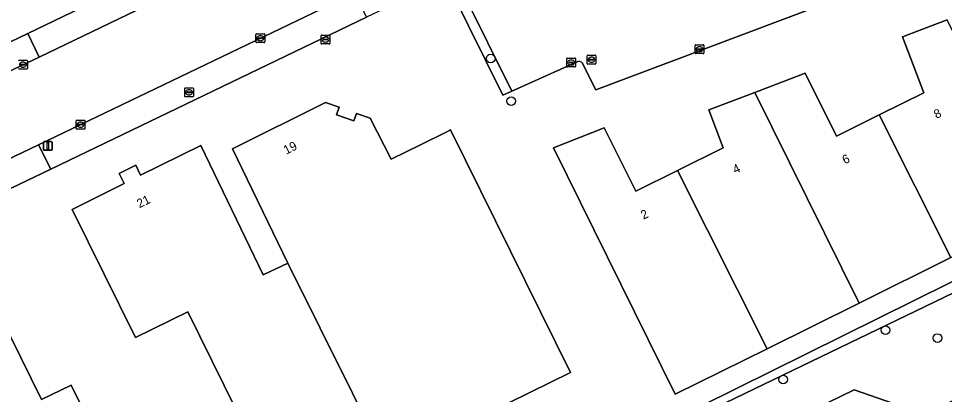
# Model space of a CAD drawing. Extents: x 157692 to 159674, y 381452 to 383291.
# Drawn here: x 158074.3 to 158178.6, y 381634.2 to 381676.6 of the extents above; entities that cross this region are included whole.
import ezdxf

# ---------------------------------------------------------------- set-up
doc = ezdxf.new("R2010")
doc.units = 0
for name, color, linetype in [('IMGEO_Boom', 7, 'Continuous'), ('IMGEO_Brandkraan', 7, 'Continuous'), ('IMGEO_Erf', 7, 'Continuous'), ('IMGEO_Groenvoorziening', 7, 'Continuous'), ('IMGEO_Kolk', 7, 'Continuous'), ('IMGEO_Lichtmast', 7, 'Continuous'), ('IMGEO_Pand', 7, 'Continuous'), ('IMGEO_Pand_nummerreeks', 7, 'Continuous'), ('IMGEO_Parkeervlak_open', 7, 'Continuous'), ('IMGEO_Rijbaan_lokaal_gesloten', 7, 'Continuous'), ('IMGEO_Rioolput', 7, 'Continuous'), ('IMGEO_Voetpad_halfverhard', 7, 'Continuous'), ('IMGEO_Voetpad_open', 7, 'Continuous')]:
    doc.layers.add(name, color=color, linetype=linetype)

msp = doc.modelspace()

# ---------------------------------------------------------------- linework, layer by layer
at = {"layer": 'IMGEO_Boom'}
for centre in [(158127.51, 381672.06), (158129.81, 381667.25), (158171.98, 381641.45), (158177.85, 381640.56), (158160.46, 381635.89)]:
    msp.add_circle(centre, 0.489, dxfattribs=at)
at = {"layer": 'IMGEO_Brandkraan'}
for p, q in [((158093.04, 381667.83), (158093.04, 381668.68)), ((158093.11, 381668.76), (158093.96, 381668.76)), ((158094.04, 381668.68), (158094.04, 381667.83)), ((158093.96, 381667.75), (158093.11, 381667.75)), ((158093.29, 381668.25), (158093.29, 381668.26)), ((158093.73, 381668.21), (158093.33, 381668.21)), ((158093.34, 381668.3), (158093.74, 381668.3)), ((158093.52, 381668.53), (158093.55, 381668.53)), ((158093.55, 381667.98), (158093.52, 381667.98)), ((158093.78, 381668.26), (158093.78, 381668.25))]:
    msp.add_line(p, q, dxfattribs=at)
for points in [[(158093.04, 381667.83), (158093.04, 381668.68)], [(158093.11, 381668.76), (158093.96, 381668.76)], [(158094.04, 381668.68), (158094.04, 381667.83)], [(158093.96, 381667.75), (158093.11, 381667.75)]]:
    msp.add_lwpolyline(points, dxfattribs=at)
for centre, radius, start, end in [((158093.11, 381668.68), 0.0765, 91.552, 178.448), ((158093.11, 381668.68), 0.0765, 91.552, 178.448), ((158093.96, 381668.68), 0.0765, 1.552, 88.448), ((158093.96, 381668.68), 0.0765, 1.552, 88.448), ((158093.11, 381667.83), 0.0765, 181.552, 268.448), ((158093.11, 381667.83), 0.0765, 181.552, 268.448), ((158093.34, 381668.26), 0.0403, 85.8775, 175.7526), ((158093.33, 381668.25), 0.0366, 178.938, 274.7102), ((158093.74, 381668.25), 0.043, 264.8664, 352.4533), ((158093.74, 381668.26), 0.0386, 1.7309, 96.639), ((158093.96, 381667.83), 0.0765, 271.552, 358.448), ((158093.96, 381667.83), 0.0765, 271.552, 358.448)]:
    msp.add_arc(centre, radius, start, end, dxfattribs=at)
for centre, major_axis, ratio, start_param, end_param in [((158093.52, 381668.25), (-0.387, 0.002), 0.722429, 4.712389, 7.853982), ((158093.55, 381668.25), (-0.39, 0.002), 0.717154, 1.570796, 4.712389)]:
    msp.add_ellipse(centre, major_axis=major_axis, ratio=ratio, start_param=start_param, end_param=end_param, dxfattribs=at)
at = {"layer": 'IMGEO_Erf'}
for points in [[(158006.88, 381609.08), (158005.9, 381627.87), (158005.47, 381636.38), (158005.22, 381641.11), (158032.78, 381654.36), (158038.28, 381657), (158060.57, 381667.76), (158067.21, 381670.95), (158069.61, 381672.13), (158075.38, 381674.88), (158095.21, 381684.45), (158107.37, 381690.34), (158121.32, 381697.1), (158122.88, 381701.31), (158109.4, 381729.27), (158106.88, 381734.58), (158102.55, 381743.61), (158102.33, 381744.05), (158099.75, 381749.47), (158099.5, 381750), (158086.3, 381777.42), (158083.31, 381783.63), (158080.66, 381789.14)], [(158209.52, 381694.97), (158139.36, 381668.54), (158137.83, 381671.58)], [(158024.82, 381594.04), (158031.77, 381579.97), (158034.87, 381573.76), (158035.24, 381573.03), (158037.88, 381567.78), (158119.21, 381608.01), (158123.9, 381610.33), (158120.64, 381617.17), (158120.43, 381617.61), (158147.17, 381630.9), (158223.29, 381668.59), (158222.29, 381671.21), (158214.04, 381692.91)], [(158137.27, 381671.68), (158129.91, 381668.4), (158128.88, 381667.94), (158123.05, 381679.74), (158122.43, 381681), (158119.71, 381679.69), (158113.54, 381676.71), (158077.96, 381659.61), (158067.11, 381654.39), (158048.67, 381645.55), (158046.69, 381644.6), (158042.44, 381642.56), (158040.6, 381641.67), (158025.19, 381634.25)], [(158179.33, 381649.62), (158169.02, 381644.5), (158158.66, 381639.36), (158148.3, 381634.22), (158134.57, 381661.98), (158140.31, 381664.26), (158143.85, 381657.12), (158148.56, 381659.46), (158153.69, 381662), (158152.07, 381666.27), (158157.26, 381668.25), (158162.95, 381670.42), (158166.47, 381663.32), (158171.28, 381665.7), (158176.31, 381668.2), (158173.91, 381674.52), (158178.92, 381676.42)], [(158104.27, 381621.43), (158093.39, 381643.51), (158087.49, 381640.61), (158080.35, 381655.06), (158086.21, 381657.98), (158085.66, 381659.1), (158087.52, 381660.04), (158088.08, 381658.9), (158094.86, 381662.26), (158101.9, 381647.68), (158104.65, 381649), (158098.44, 381661.87), (158108.91, 381667.1), (158110.46, 381666.56), (158110.16, 381665.72), (158112.11, 381665.03), (158112.4, 381665.87), (158113.95, 381665.33), (158116.3, 381660.71), (158119.67, 381662.38), (158122.42, 381663.74), (158123, 381664.03), (158136.52, 381636.69), (158115.88, 381626.52)]]:
    msp.add_lwpolyline(points, dxfattribs=at)
msp.add_lwpolyline([(158076.91, 381633.62), (158080.25, 381635.26), (158087.76, 381620.07), (158093.61, 381608.23), (158090.03, 381606.46), (158091.23, 381603.97), (158082.69, 381599.75), (158081.47, 381602.22), (158081.08, 381602.03), (158075.22, 381613.87), (158063.04, 381638.49), (158059.37, 381636.67), (158057.99, 381639.46), (158061.69, 381641.28), (158061.07, 381642.53), (158065.51, 381644.72), (158065.68, 381644.38), (158066.32, 381643.1), (158068.5, 381644.18), (158071.05, 381645.45)], close=True, dxfattribs=at)
msp.add_arc((158137.47, 381671.17), 0.548, 49.3378, 111.5714, dxfattribs=at)
at = {"layer": 'IMGEO_Groenvoorziening'}
msp.add_lwpolyline([(158463.02, 381784.54), (158461.03, 381788.17), (158441.98, 381777.74), (158416.14, 381764.39), (158259.62, 381686.58), (158254.34, 381683.97), (158223.29, 381668.59), (158147.17, 381630.9), (158120.43, 381617.61), (158120.64, 381617.17), (158179.73, 381645.71), (158182.9, 381642.9), (158254.91, 381679.12), (158392.17, 381750), (158448.48, 381779.08), (158459.69, 381785.07)], dxfattribs=at)
for points in [[(158373.93, 381726.17), (158393.92, 381735.29), (158410.81, 381742.32), (158409.27, 381746.01), (158392.39, 381738.98), (158372.39, 381729.87), (158258.55, 381675.61), (158257.98, 381676.74), (158256.56, 381676.02), (158222.08, 381658.49), (158184.33, 381640.13), (158182.9, 381642.9), (158179.73, 381645.71), (158120.64, 381617.17), (158123.9, 381610.33), (158119.21, 381608.01), (158121.49, 381605.85), (158133.24, 381611.46), (158134.78, 381618.29), (158168.47, 381634.73), (158176.33, 381632), (158260.34, 381672.04), (158264.52, 381674.03)], [(158133.24, 381611.46), (158176.33, 381632), (158168.47, 381634.73), (158134.78, 381618.29)]]:
    msp.add_lwpolyline(points, close=True, dxfattribs=at)
at = {"layer": 'IMGEO_Kolk'}
for p, q in [((158101.05, 381673.93), (158101.05, 381674.78)), ((158101.13, 381674.85), (158101.98, 381674.85)), ((158101.98, 381673.85), (158101.13, 381673.85)), ((158101.31, 381674.35), (158101.31, 381674.36)), ((158101.75, 381674.31), (158101.35, 381674.31)), ((158101.36, 381674.4), (158101.75, 381674.4)), ((158101.54, 381674.63), (158101.57, 381674.63)), ((158101.56, 381674.07), (158101.54, 381674.07)), ((158101.8, 381674.36), (158101.8, 381674.35)), ((158102.06, 381674.78), (158102.06, 381673.93)), ((158108.4, 381673.77), (158108.4, 381674.62)), ((158108.48, 381674.7), (158109.33, 381674.7)), ((158108.66, 381674.19), (158108.66, 381674.2)), ((158109.1, 381674.15), (158108.7, 381674.15)), ((158108.71, 381674.24), (158109.1, 381674.24)), ((158108.89, 381674.48), (158108.92, 381674.48)), ((158108.91, 381673.92), (158108.89, 381673.92)), ((158109.15, 381674.2), (158109.15, 381674.19)), ((158109.41, 381674.62), (158109.41, 381673.77)), ((158109.33, 381673.7), (158108.48, 381673.7)), ((158150.54, 381672.69), (158150.54, 381673.54)), ((158150.61, 381673.62), (158151.47, 381673.62)), ((158150.8, 381673.11), (158150.8, 381673.12)), ((158150.84, 381673.16), (158151.24, 381673.16)), ((158151.24, 381673.07), (158150.84, 381673.07)), ((158151.05, 381672.84), (158151.02, 381672.84)), ((158151.03, 381673.39), (158151.05, 381673.39)), ((158151.28, 381673.12), (158151.28, 381673.11)), ((158151.54, 381673.54), (158151.54, 381672.69)), ((158074.4, 381671.88), (158075.25, 381671.88)), ((158075.32, 381671.8), (158075.32, 381670.95)), ((158136.08, 381671.18), (158136.08, 381672.04)), ((158136.15, 381672.11), (158137, 381672.11)), ((158136.56, 381671.89), (158136.59, 381671.89)), ((158137.08, 381672.04), (158137.08, 381671.18)), ((158151.47, 381672.61), (158150.61, 381672.61)), ((158075.25, 381670.87), (158074.4, 381670.87)), ((158074.58, 381671.37), (158074.58, 381671.38)), ((158075.02, 381671.33), (158074.62, 381671.33)), ((158074.63, 381671.42), (158075.02, 381671.42)), ((158074.81, 381671.65), (158074.84, 381671.65)), ((158074.83, 381671.1), (158074.81, 381671.1)), ((158075.07, 381671.38), (158075.07, 381671.37)), ((158137, 381671.11), (158136.15, 381671.11)), ((158136.33, 381671.6), (158136.33, 381671.62)), ((158136.77, 381671.57), (158136.37, 381671.57)), ((158136.38, 381671.65), (158136.78, 381671.65)), ((158136.59, 381671.33), (158136.56, 381671.33)), ((158136.82, 381671.62), (158136.82, 381671.6)), ((158080.81, 381664.19), (158080.81, 381665.04)), ((158080.89, 381665.11), (158081.74, 381665.11)), ((158081.07, 381664.61), (158081.07, 381664.62)), ((158081.51, 381664.57), (158081.11, 381664.57)), ((158081.12, 381664.66), (158081.51, 381664.66)), ((158081.3, 381664.89), (158081.33, 381664.89)), ((158081.56, 381664.62), (158081.56, 381664.61)), ((158081.81, 381665.04), (158081.81, 381664.19)), ((158081.74, 381664.11), (158080.89, 381664.11)), ((158081.32, 381664.33), (158081.3, 381664.33))]:
    msp.add_line(p, q, dxfattribs=at)
for points in [[(158101.05, 381673.93), (158101.05, 381674.78)], [(158101.13, 381674.85), (158101.98, 381674.85)], [(158101.98, 381673.85), (158101.13, 381673.85)], [(158102.06, 381674.78), (158102.06, 381673.93)], [(158108.4, 381673.77), (158108.4, 381674.62)], [(158108.48, 381674.7), (158109.33, 381674.7)], [(158109.41, 381674.62), (158109.41, 381673.77)], [(158109.33, 381673.7), (158108.48, 381673.7)], [(158150.54, 381672.69), (158150.54, 381673.54)], [(158150.61, 381673.62), (158151.47, 381673.62)], [(158151.54, 381673.54), (158151.54, 381672.69)], [(158074.4, 381671.88), (158075.25, 381671.88)], [(158075.32, 381671.8), (158075.32, 381670.95)], [(158136.08, 381671.18), (158136.08, 381672.04)], [(158136.15, 381672.11), (158137, 381672.11)], [(158137.08, 381672.04), (158137.08, 381671.18)], [(158151.47, 381672.61), (158150.61, 381672.61)], [(158075.25, 381670.87), (158074.4, 381670.87)], [(158137, 381671.11), (158136.15, 381671.11)], [(158080.81, 381664.19), (158080.81, 381665.04)], [(158080.89, 381665.11), (158081.74, 381665.11)], [(158081.81, 381665.04), (158081.81, 381664.19)], [(158081.74, 381664.11), (158080.89, 381664.11)]]:
    msp.add_lwpolyline(points, dxfattribs=at)
for centre, radius, start, end in [((158101.13, 381674.78), 0.0765, 91.552, 178.448), ((158101.13, 381674.78), 0.0765, 91.552, 178.448), ((158101.13, 381673.93), 0.0765, 181.552, 268.448), ((158101.13, 381673.93), 0.0765, 181.552, 268.448), ((158101.35, 381674.36), 0.0403, 85.8775, 175.7526), ((158101.35, 381674.35), 0.0366, 178.938, 274.7102), ((158101.76, 381674.36), 0.0386, 1.7309, 96.639), ((158101.75, 381674.35), 0.043, 264.8664, 352.4533), ((158101.98, 381674.78), 0.0765, 1.552, 88.448), ((158101.98, 381674.78), 0.0765, 1.552, 88.448), ((158101.98, 381673.93), 0.0765, 271.552, 358.448), ((158101.98, 381673.93), 0.0765, 271.552, 358.448), ((158108.48, 381674.62), 0.0765, 91.552, 178.448), ((158108.48, 381674.62), 0.0765, 91.552, 178.448), ((158108.7, 381674.2), 0.0403, 85.8775, 175.7526), ((158108.7, 381674.19), 0.0366, 178.938, 274.7102), ((158109.11, 381674.2), 0.0386, 1.7309, 96.639), ((158109.1, 381674.2), 0.043, 264.8664, 352.4533), ((158109.33, 381674.62), 0.0765, 1.552, 88.448), ((158109.33, 381674.62), 0.0765, 1.552, 88.448), ((158108.48, 381673.77), 0.0765, 181.552, 268.448), ((158108.48, 381673.77), 0.0765, 181.552, 268.448), ((158109.33, 381673.77), 0.0765, 271.552, 358.448), ((158109.33, 381673.77), 0.0765, 271.552, 358.448), ((158150.62, 381673.54), 0.0765, 91.552, 178.448), ((158150.62, 381673.54), 0.0765, 91.552, 178.448), ((158150.84, 381673.12), 0.0403, 85.8775, 175.7526), ((158150.83, 381673.11), 0.0366, 178.938, 274.7102), ((158151.24, 381673.12), 0.0386, 1.7309, 96.639), ((158151.24, 381673.11), 0.043, 264.8664, 352.4533), ((158151.46, 381673.54), 0.0765, 1.552, 88.448), ((158151.46, 381673.54), 0.0765, 1.552, 88.448), ((158074.4, 381671.8), 0.0765, 91.552, 178.448), ((158074.4, 381671.8), 0.0765, 91.552, 178.448), ((158075.25, 381671.8), 0.0765, 1.552, 88.448), ((158075.25, 381671.8), 0.0765, 1.552, 88.448), ((158136.15, 381672.04), 0.0765, 91.552, 178.448), ((158136.15, 381672.04), 0.0765, 91.552, 178.448), ((158137, 381672.04), 0.0765, 1.552, 88.448), ((158137, 381672.04), 0.0765, 1.552, 88.448), ((158150.62, 381672.69), 0.0765, 181.552, 268.448), ((158150.62, 381672.69), 0.0765, 181.552, 268.448), ((158151.46, 381672.69), 0.0765, 271.552, 358.448), ((158151.46, 381672.69), 0.0765, 271.552, 358.448), ((158074.4, 381670.95), 0.0765, 181.552, 268.448), ((158074.4, 381670.95), 0.0765, 181.552, 268.448), ((158074.62, 381671.38), 0.0403, 85.8775, 175.7526), ((158074.62, 381671.37), 0.0366, 178.938, 274.7102), ((158075.03, 381671.38), 0.0386, 1.7309, 96.639), ((158075.02, 381671.37), 0.043, 264.8664, 352.4533), ((158075.25, 381670.95), 0.0765, 271.552, 358.448), ((158075.25, 381670.95), 0.0765, 271.552, 358.448), ((158136.15, 381671.19), 0.0765, 181.552, 268.448), ((158136.15, 381671.19), 0.0765, 181.552, 268.448), ((158136.38, 381671.61), 0.0403, 85.8775, 175.7526), ((158136.37, 381671.6), 0.0366, 178.938, 274.7102), ((158136.78, 381671.61), 0.043, 264.8664, 352.4533), ((158136.78, 381671.62), 0.0386, 1.7309, 96.639), ((158137, 381671.19), 0.0765, 271.552, 358.448), ((158137, 381671.19), 0.0765, 271.552, 358.448), ((158080.89, 381665.04), 0.0765, 91.552, 178.448), ((158080.89, 381665.04), 0.0765, 91.552, 178.448), ((158081.11, 381664.62), 0.0403, 85.8775, 175.7526), ((158081.11, 381664.61), 0.0366, 178.938, 274.7102), ((158081.52, 381664.62), 0.0386, 1.7309, 96.639), ((158081.51, 381664.61), 0.043, 264.8664, 352.4533), ((158081.74, 381665.04), 0.0765, 1.552, 88.448), ((158081.74, 381665.04), 0.0765, 1.552, 88.448), ((158080.89, 381664.19), 0.0765, 181.552, 268.448), ((158080.89, 381664.19), 0.0765, 181.552, 268.448), ((158081.74, 381664.19), 0.0765, 271.552, 358.448), ((158081.74, 381664.19), 0.0765, 271.552, 358.448)]:
    msp.add_arc(centre, radius, start, end, dxfattribs=at)
for centre, major_axis, ratio, start_param, end_param in [((158101.54, 381674.35), (-0.387, 0.002), 0.722429, 4.712389, 7.853982), ((158101.57, 381674.35), (-0.39, 0.002), 0.717154, 1.570796, 4.712389), ((158108.89, 381674.2), (-0.387, 0.002), 0.722429, 4.712389, 7.853982), ((158108.92, 381674.2), (-0.39, 0.002), 0.717154, 1.570796, 4.712389), ((158151.03, 381673.11), (-0.387, 0.002), 0.722429, 4.712389, 7.853982), ((158151.05, 381673.11), (-0.39, 0.002), 0.717154, 1.570796, 4.712389), ((158136.56, 381671.61), (-0.387, 0.002), 0.722429, 4.712389, 7.853982), ((158136.59, 381671.61), (-0.39, 0.002), 0.717154, 1.570796, 4.712389), ((158074.81, 381671.37), (-0.387, 0.002), 0.722429, 4.712389, 7.853982), ((158074.83, 381671.37), (-0.39, 0.002), 0.717154, 1.570796, 4.712389), ((158081.3, 381664.61), (-0.387, 0.002), 0.722429, 4.712389, 7.853982), ((158081.32, 381664.61), (-0.39, 0.002), 0.717154, 1.570796, 4.712389)]:
    msp.add_ellipse(centre, major_axis=major_axis, ratio=ratio, start_param=start_param, end_param=end_param, dxfattribs=at)
at = {"layer": 'IMGEO_Lichtmast'}
for p, q in [((158077.12, 381661.82), (158077.12, 381662.62)), ((158077.12, 381662.62), (158077.12, 381661.82)), ((158077.22, 381662.72), (158078.01, 381662.72)), ((158078.01, 381662.72), (158077.22, 381662.72)), ((158078.11, 381662.62), (158078.11, 381661.82)), ((158078.11, 381661.82), (158078.11, 381662.62)), ((158078.01, 381661.72), (158077.22, 381661.72)), ((158077.22, 381661.72), (158078.01, 381661.72))]:
    msp.add_line(p, q, dxfattribs=at)
msp.add_lwpolyline([(158077.54, 381662.6), (158077.69, 381662.6), (158077.69, 381661.85), (158077.54, 381661.85), (158077.54, 381662.6)], dxfattribs=at)
for centre, start, end in [((158077.22, 381662.62), 90, 180), ((158077.22, 381662.62), 90, 180), ((158078.01, 381662.62), 0, 90), ((158078.01, 381662.62), 360, 90), ((158077.22, 381661.82), 180, 270), ((158077.22, 381661.82), 180, 270), ((158078.01, 381661.82), 270, 0), ((158078.01, 381661.82), 270, 0)]:
    msp.add_arc(centre, 0.1, start, end, dxfattribs=at)
at = {"layer": 'IMGEO_Pand'}
for points in [[(158171.28, 381665.7), (158179.33, 381649.62), (158189.62, 381654.73), (158178.92, 381676.42), (158173.91, 381674.52), (158176.31, 381668.2)], [(158171.28, 381665.7), (158166.47, 381663.32), (158162.95, 381670.42), (158157.26, 381668.25), (158169.02, 381644.5), (158179.33, 381649.62)], [(158148.56, 381659.46), (158158.66, 381639.36), (158169.02, 381644.5), (158157.26, 381668.25), (158152.07, 381666.27), (158153.69, 381662)], [(158115.6, 381627.02), (158115.88, 381626.52), (158136.52, 381636.69), (158123, 381664.03), (158122.42, 381663.74), (158119.67, 381662.38), (158116.3, 381660.71), (158113.95, 381665.33), (158112.4, 381665.87), (158112.11, 381665.03), (158110.16, 381665.72), (158110.46, 381666.56), (158108.91, 381667.1), (158098.44, 381661.87), (158104.65, 381649)], [(158148.56, 381659.46), (158143.85, 381657.12), (158140.31, 381664.26), (158134.57, 381661.98), (158148.3, 381634.22), (158158.66, 381639.36)], [(158115.6, 381627.02), (158104.65, 381649), (158101.9, 381647.68), (158094.86, 381662.26), (158088.08, 381658.9), (158087.52, 381660.04), (158085.66, 381659.1), (158086.21, 381657.98), (158080.35, 381655.06), (158087.49, 381640.61), (158093.39, 381643.51), (158104.27, 381621.43)], [(158063.04, 381638.49), (158075.22, 381613.87), (158081.08, 381602.03), (158081.47, 381602.22), (158082.69, 381599.75), (158091.23, 381603.97), (158090.03, 381606.46), (158093.61, 381608.23), (158087.76, 381620.07), (158080.25, 381635.26), (158076.91, 381633.62), (158071.05, 381645.45), (158068.5, 381644.18), (158066.32, 381643.1), (158065.68, 381644.38), (158065.51, 381644.72), (158061.07, 381642.53), (158061.69, 381641.28)]]:
    msp.add_lwpolyline(points, close=True, dxfattribs=at)
at = {"layer": 'IMGEO_Parkeervlak_open'}
for points in [[(158137.83, 381671.58), (158139.36, 381668.54), (158209.52, 381694.97)], [(158134.94, 381680.46), (158133.34, 381683.6), (158124.44, 381679.38), (158129.91, 381668.4), (158137.27, 381671.68)]]:
    msp.add_lwpolyline(points, dxfattribs=at)
msp.add_arc((158137.47, 381671.17), 0.548, 49.3378, 111.5714, dxfattribs=at)
at = {"layer": 'IMGEO_Rijbaan_lokaal_gesloten'}
for points in [[(158122.55, 381694.38), (158120.42, 381693.34), (158076.64, 381672.23), (158070.92, 381669.49), (158068.45, 381668.33), (158061.82, 381665.1), (158039.53, 381654.39), (158034.07, 381651.69), (158020.55, 381645.25)], [(158023.86, 381637.04), (158039.26, 381644.42), (158041.13, 381645.32), (158045.41, 381647.38), (158047.38, 381648.33), (158065.78, 381657.17), (158076.59, 381662.35), (158112.23, 381679.49)]]:
    msp.add_lwpolyline(points, dxfattribs=at)
at = {"layer": 'IMGEO_Rioolput'}
for p, q in [((158138.37, 381671.51), (158138.37, 381672.36)), ((158138.44, 381672.43), (158139.3, 381672.43)), ((158138.63, 381671.93), (158138.63, 381671.94)), ((158138.67, 381671.98), (158139.07, 381671.98)), ((158139.06, 381671.89), (158138.67, 381671.89)), ((158138.86, 381672.21), (158138.88, 381672.21)), ((158139.11, 381671.94), (158139.11, 381671.93)), ((158139.37, 381672.36), (158139.37, 381671.51)), ((158139.3, 381671.43), (158138.44, 381671.43)), ((158138.88, 381671.65), (158138.85, 381671.65))]:
    msp.add_line(p, q, dxfattribs=at)
for points in [[(158138.37, 381671.51), (158138.37, 381672.36)], [(158138.44, 381672.43), (158139.3, 381672.43)], [(158139.37, 381672.36), (158139.37, 381671.51)], [(158139.3, 381671.43), (158138.44, 381671.43)]]:
    msp.add_lwpolyline(points, dxfattribs=at)
for centre, radius, start, end in [((158138.44, 381672.36), 0.0765, 91.552, 178.448), ((158138.44, 381672.36), 0.0765, 91.552, 178.448), ((158138.67, 381671.94), 0.0403, 85.8775, 175.7526), ((158138.66, 381671.93), 0.0366, 178.938, 274.7102), ((158139.07, 381671.93), 0.043, 264.8664, 352.4533), ((158139.07, 381671.94), 0.0386, 1.7309, 96.639), ((158139.29, 381672.36), 0.0765, 1.552, 88.448), ((158139.29, 381672.36), 0.0765, 1.552, 88.448), ((158138.44, 381671.51), 0.0765, 181.552, 268.448), ((158138.44, 381671.51), 0.0765, 181.552, 268.448), ((158139.29, 381671.51), 0.0765, 271.552, 358.448), ((158139.29, 381671.51), 0.0765, 271.552, 358.448)]:
    msp.add_arc(centre, radius, start, end, dxfattribs=at)
for centre, major_axis, ratio, start_param, end_param in [((158138.86, 381671.93), (-0.387, 0.002), 0.722429, 4.712389, 7.853982), ((158138.88, 381671.93), (-0.39, 0.002), 0.717154, 1.570796, 4.712389)]:
    msp.add_ellipse(centre, major_axis=major_axis, ratio=ratio, start_param=start_param, end_param=end_param, dxfattribs=at)
at = {"layer": 'IMGEO_Voetpad_halfverhard'}
msp.add_lwpolyline([(158131.15, 381685.5), (158129.74, 381684.53), (158122.43, 381681), (158123.05, 381679.74), (158128.88, 381667.94), (158129.91, 381668.4), (158124.44, 381679.38), (158133.34, 381683.6)], dxfattribs=at)
at = {"layer": 'IMGEO_Voetpad_open'}
msp.add_lwpolyline([(158125.68, 381697.64), (158122.88, 381701.31), (158121.32, 381697.1), (158107.37, 381690.34), (158095.21, 381684.45), (158075.38, 381674.88), (158076.64, 381672.23), (158120.42, 381693.34)], dxfattribs=at)
for points in [[(158076.59, 381662.35), (158077.96, 381659.61), (158113.54, 381676.71), (158112.23, 381679.49)], [(158069.61, 381672.13), (158070.92, 381669.49), (158076.64, 381672.23), (158075.38, 381674.88)], [(158065.78, 381657.17), (158067.11, 381654.39), (158077.96, 381659.61), (158076.59, 381662.35)]]:
    msp.add_lwpolyline(points, close=True, dxfattribs=at)

# ---------------------------------------------------------------- texts
at = {"layer": 'IMGEO_Pand_nummerreeks'}
for s, rotation, p in [('8', 26.3924, (158177.73, 381665.24)), ('19', 26.5826, (158104.48, 381661.22)), ('6', 26.3924, (158167.41, 381660.12)), ('4', 26.3924, (158155.07, 381659.03)), ('21', 26.0112, (158087.94, 381655.18)), ('2', 26.3924, (158144.71, 381653.89))]:
    msp.add_text(s, height=1, rotation=rotation, dxfattribs=at).set_placement(p)

doc.saveas('drawing.dxf')
